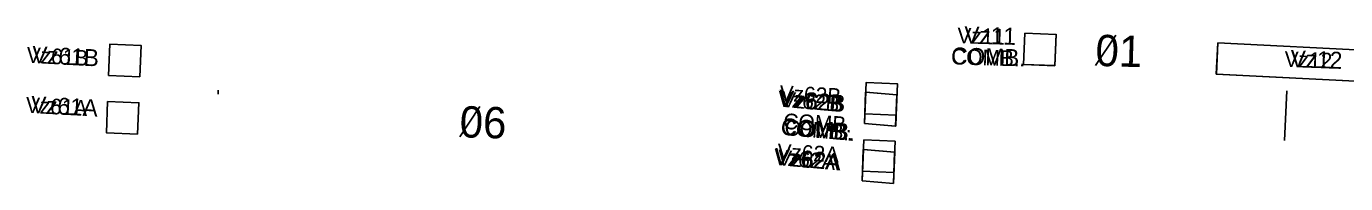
# Model space of a CAD drawing. Extents: x 647787 to 668496, y 640478 to 654412.
# Drawn here: x 659551.8 to 659804.4, y 647427.1 to 647457.2 of the extents above; entities that cross this region are included whole.
import ezdxf

# ---------------------------------------------------------------- set-up
doc = ezdxf.new("R2010")
doc.units = 0
for name, color, linetype in [('Default', 7, 'Continuous'), ('TEMP_DETECTION ZONE_Stage 2', 7, 'Continuous'), ('TEMP_DETECTION ZONE_STAGE 3', 7, 'Continuous'), ('TEMP_DETECTION_ZONE_STAGE 5', 7, 'Continuous'), ('TEMP_SIGNAL_POLES_STAGE 1B', 7, 'Continuous')]:
    doc.layers.add(name, color=color, linetype=linetype)

msp = doc.modelspace()

# ---------------------------------------------------------------- linework, layer by layer
at = {"layer": 'Default'}
for p, q in [((659756.55, 647449.75), (659760.43, 647455.53)), ((659756.55, 647449.75), (659760.43, 647455.53)), ((659756.55, 647449.75), (659760.43, 647455.53)), ((659756.55, 647449.75), (659760.43, 647455.53)), ((659756.55, 647449.75), (659760.43, 647455.53)), ((659634.79, 647436.09), (659638.66, 647441.86)), ((659634.79, 647436.09), (659638.66, 647441.86)), ((659634.79, 647436.09), (659638.66, 647441.86)), ((659634.79, 647436.09), (659638.66, 647441.86)), ((659634.79, 647436.09), (659638.66, 647441.86))]:
    msp.add_line(p, q, dxfattribs=at)
at = {"layer": 'TEMP_DETECTION ZONE_Stage 2'}
for p, q in [((659742.78, 647449.96), (659743.02, 647455.95)), ((659749.01, 647455.71), (659748.78, 647449.72)), ((659779.67, 647448.08), (659779.97, 647454.07)), ((659779.97, 647454.07), (659829.91, 647451.54)), ((659748.78, 647449.72), (659742.78, 647449.96)), ((659829.6, 647445.55), (659779.67, 647448.08))]:
    msp.add_line(p, q, dxfattribs=at)
for points in [[(659573.56, 647447.6), (659567.56, 647447.84), (659567.8, 647453.84), (659573.79, 647453.6)], [(659718.38, 647440.25), (659712.38, 647440.49), (659712.62, 647446.48), (659718.62, 647446.24)], [(659573.12, 647436.61), (659567.13, 647436.85), (659567.36, 647442.84), (659573.36, 647442.61)], [(659717.95, 647429.26), (659711.95, 647429.49), (659712.19, 647435.49), (659718.18, 647435.25)]]:
    msp.add_lwpolyline(points, close=True, dxfattribs=at)
at = {"layer": 'TEMP_DETECTION ZONE_STAGE 3'}
for p, q in [((659742.78, 647449.96), (659743.02, 647455.95)), ((659749.01, 647455.71), (659748.78, 647449.72)), ((659779.67, 647448.08), (659779.97, 647454.07)), ((659779.97, 647454.07), (659829.91, 647451.54)), ((659748.78, 647449.72), (659742.78, 647449.96)), ((659829.6, 647445.55), (659779.67, 647448.08)), ((659712.29, 647438.65), (659712.52, 647444.65)), ((659718.5, 647444.14), (659718.27, 647438.14)), ((659712.09, 647433.65), (659711.86, 647427.64)), ((659717.84, 647427.13), (659718.08, 647433.13))]:
    msp.add_line(p, q, dxfattribs=at)
for points in [[(659573.56, 647447.6), (659567.56, 647447.84), (659567.8, 647453.84), (659573.79, 647453.6)], [(659573.12, 647436.61), (659567.13, 647436.85), (659567.36, 647442.84), (659573.36, 647442.61)]]:
    msp.add_lwpolyline(points, close=True, dxfattribs=at)
for points in [[(659712.52, 647444.65), (659718.5, 647444.14)], [(659718.27, 647438.14), (659712.29, 647438.65)], [(659718.08, 647433.13), (659712.09, 647433.65)], [(659711.86, 647427.64), (659717.84, 647427.13)]]:
    msp.add_lwpolyline(points, dxfattribs=at)
at = {"layer": 'TEMP_DETECTION_ZONE_STAGE 5'}
for p, q in [((659742.78, 647449.96), (659743.02, 647455.95)), ((659742.78, 647449.96), (659743.02, 647455.95)), ((659743.02, 647455.95), (659749.01, 647455.65)), ((659743.02, 647455.95), (659749.01, 647455.65)), ((659749.01, 647455.65), (659748.77, 647449.65)), ((659749.01, 647455.65), (659748.77, 647449.65)), ((659779.74, 647448.08), (659779.97, 647454.07)), ((659779.74, 647448.08), (659779.97, 647454.07)), ((659779.97, 647454.07), (659829.91, 647451.54)), ((659779.97, 647454.07), (659829.91, 647451.54)), ((659748.77, 647449.65), (659742.78, 647449.96)), ((659748.77, 647449.65), (659742.78, 647449.96)), ((659829.68, 647445.54), (659779.74, 647448.08)), ((659829.68, 647445.54), (659779.74, 647448.08)), ((659588.56, 647445.04), (659588.52, 647444.27)), ((659588.56, 647445.04), (659588.52, 647444.27)), ((659712.31, 647438.65), (659712.55, 647444.65)), ((659712.31, 647438.65), (659712.55, 647444.65)), ((659718.53, 647444.13), (659718.3, 647438.13)), ((659718.53, 647444.13), (659718.3, 647438.13)), ((659792.73, 647435.39), (659793.21, 647444.89)), ((659792.73, 647435.39), (659793.21, 647444.89)), ((659711.88, 647427.64), (659712.11, 647433.65)), ((659711.88, 647427.64), (659712.11, 647433.65)), ((659718.1, 647433.13), (659717.86, 647427.13)), ((659718.1, 647433.13), (659717.86, 647427.13))]:
    msp.add_line(p, q, dxfattribs=at)
for points in [[(659573.56, 647447.6), (659567.56, 647447.84), (659567.8, 647453.84), (659573.79, 647453.6)], [(659573.56, 647447.6), (659567.56, 647447.84), (659567.8, 647453.84), (659573.79, 647453.6)], [(659573.12, 647436.61), (659567.13, 647436.85), (659567.36, 647442.84), (659573.36, 647442.61)], [(659573.12, 647436.61), (659567.13, 647436.85), (659567.36, 647442.84), (659573.36, 647442.61)]]:
    msp.add_lwpolyline(points, close=True, dxfattribs=at)
for points in [[(659712.55, 647444.65), (659718.53, 647444.13)], [(659712.55, 647444.65), (659718.53, 647444.13)], [(659718.3, 647438.13), (659712.31, 647438.65)], [(659718.3, 647438.13), (659712.31, 647438.65)], [(659712.11, 647433.65), (659718.1, 647433.13)], [(659712.11, 647433.65), (659718.1, 647433.13)], [(659717.86, 647427.13), (659711.88, 647427.64)], [(659717.86, 647427.13), (659711.88, 647427.64)]]:
    msp.add_lwpolyline(points, dxfattribs=at)
at = {"layer": 'TEMP_SIGNAL_POLES_STAGE 1B'}
for p, q in [((659742.78, 647449.96), (659743.02, 647455.95)), ((659743.02, 647455.95), (659749.01, 647455.65)), ((659749.01, 647455.65), (659748.77, 647449.65)), ((659779.74, 647448.08), (659779.97, 647454.07)), ((659779.97, 647454.07), (659829.91, 647451.54)), ((659748.77, 647449.65), (659742.78, 647449.96)), ((659829.68, 647445.54), (659779.74, 647448.08)), ((659712.31, 647438.65), (659712.55, 647444.65)), ((659718.53, 647444.13), (659718.3, 647438.13)), ((659711.88, 647427.64), (659712.11, 647433.65)), ((659718.1, 647433.13), (659717.86, 647427.13))]:
    msp.add_line(p, q, dxfattribs=at)
for points in [[(659573.56, 647447.6), (659567.56, 647447.84), (659567.8, 647453.84), (659573.79, 647453.6)], [(659573.12, 647436.61), (659567.13, 647436.85), (659567.36, 647442.84), (659573.36, 647442.61)]]:
    msp.add_lwpolyline(points, close=True, dxfattribs=at)
for points in [[(659712.55, 647444.65), (659718.53, 647444.13)], [(659718.3, 647438.13), (659712.31, 647438.65)], [(659712.11, 647433.65), (659718.1, 647433.13)], [(659717.86, 647427.13), (659711.88, 647427.64)]]:
    msp.add_lwpolyline(points, dxfattribs=at)

# ---------------------------------------------------------------- texts
at = {"layer": 'Default'}
for s, p in [('01', (659756.49, 647449.67)), ('01', (659756.49, 647449.67)), ('01', (659756.49, 647449.67)), ('01', (659756.49, 647449.67)), ('01', (659756.49, 647449.67)), ('06', (659634.73, 647436)), ('06', (659634.73, 647436)), ('06', (659634.73, 647436)), ('06', (659634.73, 647436)), ('06', (659634.73, 647436))]:
    msp.add_text(s, height=6, rotation=358.3326, dxfattribs=at).set_placement(p)
at = {"layer": 'TEMP_DETECTION ZONE_Stage 2'}
for s, rotation, p in [('Vz11', 358.2413, (659730.04, 647454.01)), ('Vz61B', 356.9063, (659551.78, 647450.29)), ('COMB.', 358.2413, (659728.86, 647449.98)), ('Vz12', 357.8394, (659792.69, 647449.49)), ('Vz62B', 356.9063, (659695.97, 647442.98)), ('Vz61A', 356.9063, (659551.63, 647440.7)), ('COMB.', 356.9063, (659696.71, 647437.6)), ('Vz62A', 356.9063, (659695.56, 647431.8))]:
    msp.add_text(s, height=3, rotation=rotation, dxfattribs=at).set_placement(p)
at = {"layer": 'TEMP_DETECTION ZONE_STAGE 3'}
for s, rotation, p in [('Vz11', 358.2413, (659730.04, 647454.01)), ('Vz61B', 356.9063, (659551.78, 647450.29)), ('COMB.', 358.2413, (659728.86, 647449.98)), ('Vz12', 357.8394, (659792.69, 647449.49)), ('Vz61A', 356.9063, (659551.63, 647440.7)), ('Vz62B', 355.1459, (659696.34, 647441.83)), ('COMB.', 355.1459, (659696.92, 647436.43)), ('Vz62A', 355.1459, (659695.59, 647430.67))]:
    msp.add_text(s, height=3, rotation=rotation, dxfattribs=at).set_placement(p)
at = {"layer": 'TEMP_DETECTION_ZONE_STAGE 5'}
for s, rotation, p in [('Vz11', 358.2413, (659730.04, 647454.01)), ('Vz11', 358.2413, (659730.04, 647454.01)), ('Vz61B', 356.9063, (659551.78, 647450.29)), ('Vz61B', 356.9063, (659551.78, 647450.29)), ('COMB.', 358.2413, (659728.86, 647449.98)), ('COMB.', 358.2413, (659728.86, 647449.98)), ('Vz12', 357.8394, (659792.69, 647449.49)), ('Vz12', 357.8394, (659792.69, 647449.49)), ('Vz61A', 356.9063, (659551.63, 647440.7)), ('Vz61A', 356.9063, (659551.63, 647440.7)), ('Vz62B', 355.0374, (659695.63, 647441.91)), ('Vz62B', 355.0374, (659695.63, 647441.91)), ('COMB.', 355.0374, (659696.2, 647436.51)), ('COMB.', 355.0374, (659696.2, 647436.51)), ('Vz62A', 355.0374, (659694.86, 647430.75)), ('Vz62A', 355.0374, (659694.86, 647430.75))]:
    msp.add_text(s, height=3, rotation=rotation, dxfattribs=at).set_placement(p)
at = {"layer": 'TEMP_SIGNAL_POLES_STAGE 1B'}
for s, rotation, p in [('Vz11', 358.2413, (659731.36, 647453.98)), ('Vz61B', 356.9063, (659552.83, 647450.23)), ('COMB.', 358.2413, (659728.88, 647449.98)), ('Vz12', 357.8394, (659793.85, 647449.45)), ('Vz61A', 356.9063, (659552.62, 647440.65)), ('Vz62B', 355.0374, (659695.76, 647441.89)), ('COMB.', 355.0374, (659696.22, 647436.5)), ('Vz62A', 355.0374, (659694.92, 647430.74))]:
    msp.add_text(s, height=3.25, rotation=rotation, dxfattribs=at).set_placement(p)

doc.saveas('drawing.dxf')
